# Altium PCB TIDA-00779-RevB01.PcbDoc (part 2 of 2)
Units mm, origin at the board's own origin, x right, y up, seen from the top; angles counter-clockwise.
Board outline 215 x 145 mm, 2 copper layers (Top Layer, Bottom Layer), stack 1.575 mm thick; 136 components, 56 nets, 280 pads, 32 vias.
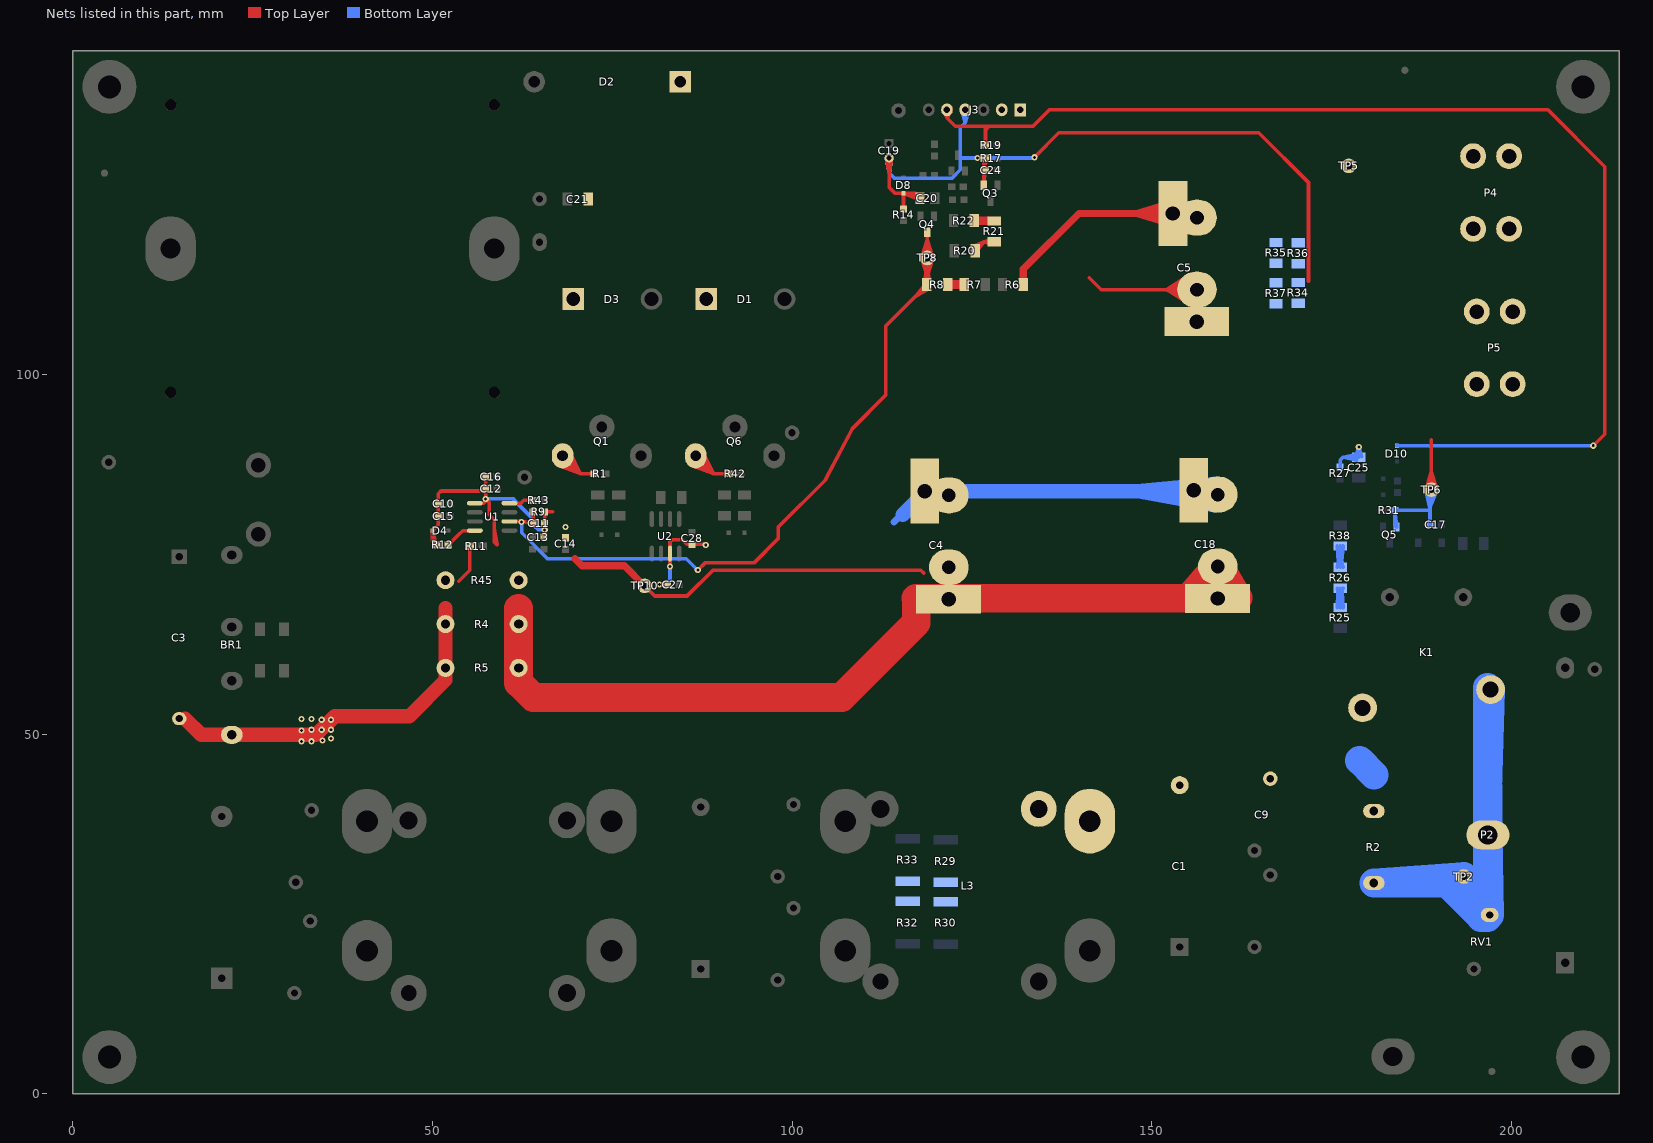
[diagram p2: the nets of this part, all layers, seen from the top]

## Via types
v1: diameter 0.864, hole 0.406, Top Layer to Bottom Layer, 32 vias

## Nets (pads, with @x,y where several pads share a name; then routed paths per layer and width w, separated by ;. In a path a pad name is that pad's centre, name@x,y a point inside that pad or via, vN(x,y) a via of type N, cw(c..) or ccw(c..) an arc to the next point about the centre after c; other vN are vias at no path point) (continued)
NetR7_1: R7.1 R8.2 | length 32.5
  Top Layer w0.5: R8.2@121.618,112.101 R7.1@123.778,112.127 ; R8.2@121.618,112.899 R7.1@123.778,112.873 ; R8.2@121.755,112.114 R7.1@123.778,112.873 ; R8.2@121.755,112.886 R7.1@123.778,112.127 ; R7.1@123.913,112.102 R8.2@121.8,112.5 ; R7.1@123.913,112.898 R8.2@121.8,112.5 ; R8.2@121.65,112.5 R7.1@123.8,112.5 ; R8.2@121.65,112.5 R7.1@123.778,112.873 ; R8.2@121.65,112.5 R7.1@123.778,112.127 ; R8.2@121.65,112.5 R7.1@123.95,112.5 R8.2@121.8,112.5 ; R7.1@123.8,112.5 121.687,112.102 R7.1@123.8,112.5 ; R7.1@123.8,112.5 121.687,112.898 R7.1@123.8,112.5
NetR12_2: R12.2 U1.4 | length 7.6
  Top Layer w0.5: R12.2@52.2,76.3 54.195,78.295 ; R12.2@52.225,76.3 53.736,77.836 ; U1.4@55.1,78.295 54.195,78.295 ; U1.4@55.9,78.295 54.195,78.295
NetR20_1: R20.1 R21.1 | length 11.3
  Top Layer w0.5: R20.1@125.246,117.819 126.7,118.45 ; R20.1@125.45,117.2 126.7,118.45 ; R20.1@125.45,117.475 126.7,118.45 ; R20.1@125.734,117.193 126.7,118.45 ; R21.1@127.754,118.056 126.7,118.45 ; R21.1@127.754,118.844 126.7,118.45 ; R21.1@127.825,118.45 126.7,118.45 ; R21.1@128.1,118.45 126.7,118.45
NetR21_2: R21.2 R22.2 | length 35.1
  Top Layer w0.5: R22.2@125.315,121.002 R21.2@127.476,121.011 ; R22.2@125.333,121.8 R21.2@127.498,121.694 ; R22.2@125.441,121.01 R21.2@127.498,121.694 ; R22.2@125.458,121.785 R21.2@127.476,121.011 ; R21.2@127.788,120.952 R22.2@125.675,121.35 ; R21.2@127.788,121.748 R22.2@125.675,121.35 ; R21.2@127.825,121.35 R22.2@125.675,121.35 ; R21.2@128.1,121.35 125.4,121.35 R22.2@125.35,121.4 ; R22.2@125.35,121.4 R21.2@127.502,121.35 ; R22.2@125.35,121.4 R21.2@127.498,121.694 ; R22.2@125.35,121.4 R21.2@127.476,121.011 ; R22.2@125.35,121.4 R21.2@127.501,121.35 ; R21.2@127.502,121.35 125.378,121.001 R21.2@127.501,121.35 ; R21.2@127.502,121.35 125.396,121.797 R21.2@127.501,121.35
NetR25_1: R25.1 R26.1 | length 24.4
  Bottom Layer w0.5: R25.1@175.8,67.581 R26.1@175.896,69.761 ; R25.1@175.802,67.637 176.2,69.75 R25.1@176.598,67.637 ; R26.1@175.802,70.263 176.2,68.15 R26.1@176.598,70.263 ; R25.1@175.811,67.692 R26.1@176.504,69.761 ; R26.1@176.2,70.3 R25.1@176.2,67.6 ; R25.1@176.589,67.692 R26.1@175.896,69.761 ; R25.1@176.6,67.581 R26.1@176.504,69.761 ; R26.1@175.896,69.761 R25.1@176.2,67.6 ; R25.1@176.2,67.6 R26.1@176.504,69.761
NetR26_2: R26.2 R38.1 | length 29.4
  Bottom Layer w0.5: R38.1@175.8,76.161 175.942,73.982 ; R26.2@175.802,73.237 176.2,75.35 ; R38.1@175.802,76.113 176.2,74 R38.1@176.598,76.113 ; R38.1@175.809,76.067 176.458,73.982 ; R26.2@176.2,73.2 R38.1@176.2,76.15 ; R38.1@176.591,76.067 175.942,73.982 ; R26.2@176.598,73.237 176.2,75.35 ; R38.1@176.6,76.161 176.458,73.982 ; 175.942,73.982 R38.1@176.2,76.15 ; 176.2,75.35 R38.1@176.2,76.15 ; 176.2,75.35 175.813,76.05 176.2,75.35 ; 176.2,75.35 176.587,76.05 176.2,75.35 ; 176.2,75.35 R38.1@176.2,76.15 ; R38.1@176.2,76.15 176.458,73.982
NetR29_2: R29.2 R30.1 R32.1 R33.2
NetR34_2: R34.2 R35.1 R36.1 R37.2
NetR43_1: R43.1 U1.8 | length 5.7
  Top Layer w0.5: U1.8@60.6,82.105 62.305,82.105 ; U1.8@61.4,82.105 62.305,82.105 ; R43.1@63.975,82.5 62.7,82.5 ; R43.1@64,82.5 62.7,82.5 ; 62.305,82.105 62.7,82.5
PFC_ON: D10.2 J3.5 R19.1 | length 171.2
  Top Layer w0.5: J3.5@120.998,136.878 121.56,135.64 ; J3.5@122.122,136.878 121.56,135.64 ; R19.1@126.9,131.9 126.9,134 ; 126.9,134.2 126.9,134 ; 127.3,134.4 126.9,134 ; v1(211.4,90.1) 213,91.7 213,128.9 205.1,136.8 135.8,136.8 133.5,134.5 122.7,134.5 121.56,135.64 ; 121.56,135.64 121.56,137 121.56,135.64
  Bottom Layer w0.5: D10.2@184.1,90.1 v1(211.4,90.1)
PGND: C4.2 C5.2 C10.2 C11.2 C12.2 C13.2 C14.2 C15.2 C16.2 C17.2 C18.2 C19.2 C20.2 C24.2 C25.2 C27.2 C28.1 D4.2 D8.1 J3.4 P5.1 P5.2 P5.3 P5.4 Q1.3 Q3.2 Q5.2 Q6.3 R1.2 R4.1 R5.1 R9.1 R12.1 R14.2 R17.1 R27.1 R31.1 R34.1 R37.1 R42.2 R45.1 TP6.1 TP10.1 U1.1 U2.3 | length 610.4
  Top Layer w0.5: R12.1@50.6,76.3 50,76.9 ; U1.1@55.9,82.105 57.105,82.105 ; v1@57.4,82.4 57.105,82.105 ; C16.2@57.4,85.8 C12.2@57.4,84.1 ; 58.6,78.557 59,76.325 ; 59,76.3 58.6,76.7 58.6,79.8 57.9,80.5 57.9,82.2 v1(57.4,82.7) C12.2@57.4,84.1 ; 61.98,67.5 62,67.52 ; C13.2@65.5,77.4 65.6,77.5 v1(65.6,78.4) ; C13.2@65.525,77.4 v1(65.6,78.4) ; R9.1@65.625,80.9 66.6,80.9 ; 66.7,80.9 66.6,80.9 ; Q1.3@67.451,87.382 70.6,86.2 ; Q1.3@67.664,87.84 70.6,86.2 ; Q1.3@67.94,88.258 70.6,86.2 ; Q1.3@68.1,88.45 70.6,86.2 ; Q1.3@68.1,88.7 70.6,86.2 ; Q1.3@68.274,88.629 70.6,86.2 ; Q1.3@68.661,88.948 70.6,86.2 ; Q1.3@69.094,89.208 70.6,86.2 ; R1.2@72.475,86.2 70.6,86.2 ; R1.2@72.5,86.2 70.6,86.2 ; TP10.1@79.5,70.6 80.9,69.2 85.4,69.2 89,72.8 117.9,72.8 118.3,72.4 ; v1(81.574,70.8) C27.2@82.7,70.8 ; v1(83.035,73.3) U2.3@83.035,75.1 83.035,76.735 83.3,77 84.8,77 85.4,76.4 C28.1@86.1,76.4 87.9,76.4 v1(88,76.3) ; Q6.3@85.951,87.382 89.1,86.2 ; Q6.3@86.164,87.84 89.1,86.2 ; Q6.3@86.44,88.258 89.1,86.2 ; Q6.3@86.6,88.45 89.1,86.2 ; Q6.3@86.6,88.7 89.1,86.2 ; Q6.3@86.774,88.629 89.1,86.2 ; Q6.3@87.161,88.948 89.1,86.2 ; Q6.3@87.594,89.208 89.1,86.2 ; 89.3,86.2 R42.2@91.275,86.2 ; R42.2@91.3,86.2 89.1,86.2 ; C19.2@113.126,130.067 113.5,127.975 ; C19.2@113.874,130.067 113.5,127.975 ; R14.2@115.5,123 D8.1@115.5,125.2 ; R14.2@115.5,123.4 D8.1@115.5,125.2 ; C20.2@117.683,124.298 D8.1@115.5,125.2 ; C20.2@117.8,124.5 117.1,125.2 ; C20.2@117.856,125.046 D8.1@115.5,125.2 ; Q3.2@126.647,126.3 R17.1@126.647,129.847 ; Q3.2@126.647,126.386 C24.2@126.875,128.4 ; C24.2@126.647,128.033 126.875,130.1 v1(125.8,130.1) R17.1@126.9,130.1 ; C24.2@126.647,128.45 126.647,126.525 C24.2@126.875,128.4 ; v1(133.7,130.2) 137.1,133.6 164.9,133.6 171.8,126.7 171.8,113 ; 141.33,113.47 143,111.8 C5.2@156.3,111.8 ; C5.2@155.417,109.641 152.05,111.8 ; C5.2@155.417,113.959 152.05,111.8 ; C5.2@155.667,110.092 152.05,111.8 ; C5.2@155.667,113.508 152.05,111.8 ; C5.2@155.855,110.565 152.05,111.8 ; C5.2@155.855,113.035 152.05,111.8 ; C5.2@155.98,111.053 152.05,111.8 ; C5.2@155.98,112.547 152.05,111.8 ; C5.2@156.042,111.55 152.05,111.8 ; C5.2@156.042,112.05 152.05,111.8 ; C5.2@156.05,111.8 152.05,111.8 ; TP6.1@188.143,84.117 188.9,86.516 ; TP6.1@188.634,84.014 188.9,86.516 ; TP6.1@188.9,84 188.9,90.9 ; TP6.1@189.166,84.014 188.9,86.516 ; TP6.1@189.657,84.117 188.9,86.516 ; 50,76.9 R12.1@50.575,76.3 ; 50,76.9 R12.1@50.575,76.3 ; 50,76.9 R12.1@50.575,76.3 ; 50,76.9 D4.2@50,78.3 ; 50,76.9 D4.2@50,78.3 ; D4.2@50,78.3 R12.1@50.575,76.3 ; D4.2@50,78.3 R12.1@50.575,76.3 ; D4.2@50,78.3 50.8,79.1 ; 50.8,79.1 C15.2@50.8,80.3 ; 50.8,79.1 C15.2@50.8,80.3 ; C15.2@50.8,80.3 C10.2@50.8,82 ; C15.2@50.8,80.3 C10.2@50.8,82 ; C10.2@50.8,82 50.8,83.4 51.2,83.8 57.1,83.8 C12.2@57.4,84.1 ; 57.105,82.105 56.7,82.105 57.105,82.105 ; v1(65.6,78.4) C11.2@65.6,79.3 ; v1(65.6,78.4) C11.2@65.6,79.3 ; C11.2@65.6,79.3 R9.1@65.6,80.9 ; C11.2@65.6,79.3 R9.1@65.6,80.9 ; R9.1@65.6,80.9 66.6,80.9 ; 113.5,127.975 C19.2@113.5,130.1 113.5,126 114.3,125.2 ; 114.3,125.2 D8.1@115.5,125.2 ; 114.3,125.2 D8.1@115.5,125.2 ; D8.1@115.5,125.2 C20.2@117.8,124.665 ; D8.1@115.5,125.2 117.1,125.2 ; 117.1,125.2 C20.2@117.8,124.665 ; 117.1,125.2 117.961,125.015 117.1,125.2 ; 117.1,125.2 117.505,124.418 117.1,125.2 ; 117.1,125.2 C20.2@117.8,124.665 ; R17.1@126.647,129.847 R17.1@126.9,130.1 ; R17.1@126.647,129.847 C24.2@126.875,128.4 ; C24.2@126.875,128.4 R17.1@126.9,130.1 ; R14.2@115.5,123.025 115.5,125 R14.2@115.5,123.025
  Top Layer w1: 69.8,74.4 70.8,73.4 76.7,73.4 TP10.1@79.5,70.6
  Top Layer w4: 61.98,67.5 61.98,57.12 64,55.1 106.9,55.1 117.275,65.475 C4.2@117.275,68.881 ; 117.241,68.881 C4.2@117.275,68.881 ; 142.665,68.881 C18.2@156.666,68.85 ; C18.2@158.95,73.3 C18.2@155.166,68.95 ; C18.2@159.45,73.3 162.05,68.95 C18.2@155.166,68.95 ; C4.2@117.275,68.881 155.097,68.881 C18.2@155.166,68.95
  Bottom Layer w0.5: v1(57.4,82.7) 61.3,82.7 ; 61.2,82.7 64.2,79.7 64.2,78.9 64.7,78.4 v1(65.6,78.4) ; v1(81.574,70.8) 82.4,70.8 83.035,71.435 v1(83.035,73.3) ; C19.2@113.127,130.066 113.5,128.05 ; C19.2@113.873,130.066 113.5,128.05 ; J3.4@123.531,136.917 124.1,135 ; J3.4@124.669,136.917 124.1,135 ; v1(133.7,130.2) 133.6,130.1 v1(125.8,130.1) 123.5,130.1 123.4,130 ; R27.1@176.2,87.1 176.2,88.1 ; R27.1@176.2,87.125 176.2,88.1 ; C25.2@178.404,88.557 v1(178.8,89.9) ; C25.2@178.483,88.102 176.6,88.5 ; C25.2@178.483,88.898 176.6,88.5 ; C25.2@178.525,88.5 176.6,88.5 ; C25.2@179.196,88.557 v1(178.8,89.9) ; Q5.2@183.8,79.125 R31.1@183.8,81.1 ; R31.1@183.8,80.99 184.053,79.025 R31.1@183.8,80.997 ; R31.1@183.825,81.1 185.8,81.1 ; Q5.2@184.053,78.8 183.8,79.053 R31.1@183.8,81.1 ; TP6.1@188.136,83.944 188.7,81.474 ; TP6.1@188.634,84.007 188.7,81.474 ; C17.2@188.7,79.1 188.7,81.1 ; TP6.1@189.164,83.965 188.7,81.474 ; TP6.1@189.646,83.825 188.7,81.474 ; 113.5,128.05 C19.2@113.5,130.1 113.5,128.05 ; 113.5,128.05 114.25,127.3 122.25,127.3 123.4,128.45 123.4,130 ; 123.4,130 123.4,134.3 124.1,135 ; 124.1,135 124.1,137 124.1,135 ; 176.2,88.1 176.6,88.5 ; 176.6,88.5 C25.2@178.8,88.5 v1(178.8,89.9) ; R31.1@183.8,81.1 188.7,81.1 ; 188.7,81.1 188.7,83.8 TP6.1@188.9,84 188.7,81.474
  other v1: 68.5,78.8
RLY-N: ?.4@134.3,39.6 C1.2 C9.1 K1.4 L3.4 R2.2 | length 4.8
  Bottom Layer w4: L3.4@141.4,37.9 L3.4@142.8,39.3 ; 178.9,46.33 180.9,44.33
RLY-P: K1.3 P2.1 R2.1 RV1.1 TP2.1 | length 175.7
  Bottom Layer w4: 196.7,42.158 K1.3@197.127,56.19 ; 196.7,49.975 P2.1@196.749,35.975 ; K1.3@196.7,56.47 P2.1@196.7,35.975 ; 191,29.3 195.8,24.5 ; 191,29.3 TP2.1@193.4,30.2 ; 191,29.3 TP2.1@193.4,30.2 ; 191,29.3 TP2.1@193.4,30.2 ; 191,29.3 TP2.1@193.4,30.2 ; 191,29.3 196.75,24.85 TP2.1@193.4,30.2 ; 191,29.3 181.4,29.3 TP2.1@193.4,30.2 ; 191,29.3 R2.1@180.9,29.3 TP2.1@193.4,30.2 ; TP2.1@193.4,30.2 195.8,24.5 ; 195.8,24.5 RV1.1@196.7,24.5 ; RV1.1@196.7,24.5 P2.1@196.7,35.975 ; RV1.1@196.7,24.5 P2.1@196.749,35.975 ; P2.1@196.7,35.975 RV1.1@197,24.85 P2.1@196.749,35.975
RTN: BR1.4 C3.2 R4.2 R5.2 R11.1 R45.2 | length 67
  Top Layer w0.5: 53.65,71.25 55.2,72.8 R11.1@55.2,76.1
  Top Layer w2: C3.2@15.6,52.15 17.85,49.9 ; BR1.4@21.85,49.9 17.85,49.9 ; BR1.4@22.35,49.9 29.6,49.9 ; 51.82,67.5 51.82,57.52 46.8,52.5 36.4,52.5 33.8,49.9 BR1.4@22.1,49.9 17.85,49.9
  other v1: 31.8,49 33.2,49 34.7,49.1 35.9,49.4 31.8,50.5 33.2,50.6 34.6,50.6 35.9,50.6 34.6,52 35.9,52 31.8,52.1 33.2,52.1
VDCBUS: C4.1 C5.1 C18.1 C21.1 D1.2 D2.1 D3.2 P4.1 P4.2 P4.3 P4.4 R6.2 R35.2 R36.2 TP5.1 | length 189.3
  Top Layer w1: R6.2@132.15,112.5 132.15,114.65 ; R6.2@132.15,112.775 132.15,114.65 ; C5.1@152.725,120.905 147.95,122.388 ; C5.1@152.725,123.871 147.95,122.388 ; C5.1@152.925,121.889 147.95,122.388 ; C5.1@152.925,122.887 147.95,122.388 ; C5.1@152.95,122.388 139.888,122.388 132.15,114.65
  Bottom Layer w1: 114.162,79.5 C4.1@118.45,83.788
  Bottom Layer w2: 115.4,80.5 C4.1@118.1,83.2 ; C4.1@118.1,83.788 C4.1@118.45,83.788 C18.1@156.274,83.788 ; C18.1@156.55,83.512 C18.1@156.274,83.788 ; C18.1@158.328,81.935 C18.1@155.85,83.888 ; C18.1@158.733,81.816 150.413,83.788 ; C18.1@158.783,81.809 147.848,83.788 ; C18.1@158.871,84.798 C18.1@155.85,83.888 ; C18.1@158.904,84.799 150.413,83.788 ; C18.1@158.915,84.8 147.848,83.788 ; 147.848,83.788 C18.1@158.95,83.3 ; 147.848,83.788 C18.1@155.85,83.888 ; 150.413,83.788 C18.1@158.95,83.3 ; C18.1@155.85,83.888 C18.1@158.95,83.3 ; C18.1@156.274,83.788 C18.1@158.95,83.3 ; C18.1@156.274,83.788 158.802,84.793 C18.1@156.274,83.788 ; C18.1@156.274,83.788 158.284,81.956 C18.1@156.274,83.788 ; C18.1@156.274,83.788 C18.1@158.95,83.3
VN: J3.2
VP: J3.1
VSENSE: C11.1 Q4.3 R8.1 R9.2 TP8.1 U1.6 | length 141.2
  Top Layer w0.5: U1.6@60.6,79.565 v1@62.335,79.565 ; U1.6@61.4,79.565 v1@62.335,79.565 ; C11.1@63.975,79.3 v1(62.4,79.5) ; v1(86.9,72.8) 87.9,73.8 94.7,73.8 98.1,77.2 98.1,78.8 104.6,85.3 108.4,92.5 113,97.1 113,106.7 118.8,112.5 Q4.3@118.8,119.8 ; TP8.1@118.043,116.083 118.8,113.684 ; TP8.1@118.043,116.317 118.8,118.716 ; R8.1@118.353,112.821 118.8,114.926 ; R8.1@118.462,112.503 117.061,110.761 ; TP8.1@118.534,116.186 118.8,113.684 ; TP8.1@118.534,116.214 118.8,118.716 ; R8.1@118.75,112.225 117.061,110.761 ; R8.1@118.75,112.775 118.8,114.926 ; 118.8,117.65 Q4.3@118.8,119.575 ; R8.1@118.984,111.901 117.061,110.761 ; TP8.1@119.066,116.186 118.8,113.684 ; TP8.1@119.066,116.214 118.8,118.716 ; R8.1@119.149,112.803 118.8,114.926 ; TP8.1@119.557,116.083 118.8,113.684 ; TP8.1@119.557,116.317 118.8,118.716 ; v1@62.335,79.565 v1(62.4,79.5) ; v1(62.4,79.5) 63.8,79.5 C11.1@64,79.3 ; C11.1@64,79.3 R9.2@64,80.9 C11.1@64,79.3 ; 118.8,113.684 TP8.1@118.8,116.2 118.8,118.716
  Bottom Layer w0.5: v1(62.4,79.5) 62.4,78 66,74.4 85.3,74.4 v1(86.9,72.8)
pads on no net: FID1.1 FID2.1 FID3.1 H1.1 H2.1 H3.1 H4.1 L1.3 U2.1 U2.8

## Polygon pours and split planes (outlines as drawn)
RTN on Bottom Layer "Bottom Layer-No Net 13" (solid, pour order 73): 14.9,53.1 36,53.1 36.9,52.2 36.9,49.7 35.9,48.7 35.6,48.4 17.8,48.4 16.4,48.4 14.4,50.4 14.4,52.6 14.754,52.954
RLY-N on Bottom Layer "Bottom Layer-No Net 5" (solid, pour order 50): 132.4,33.3 154.9,33.3 159.9,38.3 169.6,38.3 169.5,38.4 184.7,38.4 186,39.7 186,53.9 183.8,56.1 144.5,56.1 131.3,42.9 131.3,34.4
NetC1_1 on Bottom Layer "Top Layer-No Net 3" (solid, pour order 46): 176,24.8 177.1,23.7 188.4,23.7 192.6,19.5 201.3,19.5 204,22.2 213,22.2 213.4,21.8 213.4,15.4 206.9,11.1 178.3,11.1 176.2,13.2 146.1,13.2 142.8,9.9 133,9.9 131.4,11.5 131.4,23.5 132.7,24.8
NetC2_2 on Bottom Layer "M1 Board Outline-No Net" (solid, pour order 39): 112.2,47.7 117.3,42.6 123.4,42.6 123.6,42.4 123.6,35.4 123,34.9 114.4,34.9 112.9,33.4 103.5,33.4 102.4,34.5 94.6,34.5 89.9,29.8 66.8,29.8 65,31.6 65,45.6 67.1,47.7
NetBR1_3 on Bottom Layer "Bottom Layer-No Net 4" (solid, pour order 42): 38.9,24.4 48.2,24.4 50.4,22.2 50.4,4.3 48.1,2 18,2 0.9,19.1 0.9,62.9 2.5,64.5 15.3,64.5 19.8,60 23.7,60 24.1,59.6 24.1,55.8 23.6,55.3 12.8,55.3 11.3,53.8 11.3,48.4 14.9,44.8 14.9,31.8 26.9,19.8 34.3,19.8
NetBR1_2 on Bottom Layer "Bottom Layer-No Net 3" (solid, pour order 41): 18.6,45.4 46.6,45.4 49.7,42.3 49.7,35.6 47.5,33.4 19.9,33.4 18.2,35.1 18.2,45
NetF1_2 on Bottom Layer "Top Layer-No Net 16" (solid, pour order 64): 205.3,72.5 205.3,57.3 205.8,56.8 212.2,56.8 212.9,57.5 212.9,75.7 212.2,76.4 209.2,76.4
VDCBUS on Bottom Layer "Bottom Layer-No Net" (solid, pour order 38): 144.1,133.2 115.5,104.6 115.5,93.7 111.8,90 111.8,80.2 113,79 117.2,79 160.8,79.1 162.4,80.7 162.4,95.7 158.8,99.3 149.1,99.3 146.5,101.9 146.5,115.7 148.5,117.7 206.5,117.7 207.8,119 207.8,129 203.6,133.2
VDCBUS on Bottom Layer "Bottom Layer-No Net 11" (solid, pour order 70): 68.2,125.8 69.2,126.8 103.2,126.8 117.5,112.5 124.3,112.5 115,103.2 108.2,103.2 107,104.4 102.9,104.4 104.6,106.1 104.6,112.8 101.4,116 97.1,116 93.8,112.7 93.8,107.5 93.2,106.9 87.794,106.9 86.2,108.494 86.2,115.2 85.4,116 77.9,116 75.1,113.2 75.1,109 74.4,108.3 74.2,108.5 68.2,108.5
NetBR1_1 on Bottom Layer "Bottom Layer-No Net 12" (solid, pour order 71): 20.5,79.4 20.5,73.9 20.9,73.5 26.9,73.5 27.3,73.9 27.3,78.8 26.6,79.5 20.6,79.5 20.5,79.4
NetC3_1 on Bottom Layer "Bottom Layer-No Net 2" (solid, pour order 40): 28.5,142.8 66.786,142.901 67.7,141.9 67.7,135.1 62.5,130 42.4,130 37.6,125.5 37.7,89.7 33,85 18.2,84.9 16.8,83.6 16.8,73.85 16.414,73.4 3.6,73.4 2.6,74.4 2.6,116.8 27.4,141.6
VDCBUS on Bottom Layer "Bottom Layer-No Net 10" (solid, pour order 69): 67.6,113.2 67.6,99.1 68.7,98 69,97.7 90.5,97.7 102.5,97.7 112.9,87.3 117.5,91.9 117.5,103.1 117.5,104.8 116.9,105.4 116.8,105.5 95.7,105.5 93,108.2 93,112.8 92.4,113.4 86.9,113.4 86.1,112.6 86.1,109.194 86.8,108.494 87.2,108.094 87.2,105.6 86.9,105.6 86.7,105.4 75.5,105.4 74.4,106.5 74.4,112.9 73.4,113.9 68.3,113.9 67.6,113.2
PGND on Bottom Layer "Bottom Layer-No Net 7" (solid, pour order 66): 122.5,75.89 108.81,75.89 101.1,83.6 94.1,83.6 87.2,90.5 84.1,90.5 83.7,90.1 83.7,86 81.4,83.7 74.6,83.7 73.3,85 73.3,87 69.4,90.9 66.9,90.9 66,90 66,78.6 67.5,77.1 84.3,77.1 88.9,72.5 95.4,72.5 105.5,62.4 124.4,62.4 130.6,68.6 130.6,69.8
PGND on Bottom Layer "Bottom Layer-No Net 9" (solid, pour order 65): 160.7,75.8 119.6,75.8 118.2,74.4 116.5,72.7 116.5,67.49 116.5,66.7 117.1,66.1 117.69,66.69 161.8,66.69 163.29,66.69 163.9,67.3 163.9,75 163.1,75.8
PGND on Bottom Layer "Bottom Layer-No Net 8" (solid, pour order 56): 171.2,110.5 164,110.5 161.8,112.7 160.3,114.2 155.1,114.2 152.8,114.2 151.8,113.2 151.8,105 152.1,104.7 169.7,104.7 171.2,106.2
RLY-P on Bottom Layer "Bottom Layer-No Net 6" (solid, pour order 52): 178,35 186,35 189.3,38.3 189.3,60 190.3,61 200.9,61 201.8,60.1 201.8,24.8 199.7,22.7 194.6,22.7 192.3,25 190.4,26.9 180.6,26.9 179,26.9 177.6,28.3 177.6,34.6 178,35
NetC2_1 on Bottom Layer "Top Layer-No Net 2" (solid, pour order 45): 69.8,24.8 88.7,24.8 91.9,21.6 101.9,21.6 104.5,24.2 112.4,24.2 115,21.6 122.8,21.6 123.5,20.9 123.5,4.7 120.8,2 67.6,2 66.1,3.5 66.1,21.1
VDCBUS on Top Layer "Top Layer-No Net 9" (solid, remove dead copper, pour order 67): 82.1,143.3 80.1,141.3 80.1,129.4 69.7,121.9 69.7,116.3 67.7,114.3 67.7,109 68.1,108.6 74.7,108.6 75,108.9 75,114.3 76.6,115.9 85.6,115.9 86.1,115.4 86.1,109.2 86.6,108.7 92.5,108.7 93,109.2 93,114.1 101.546,122.646 101.546,141.854 100.1,143.3
NetBR1_2 on Top Layer "Top Layer-No Net 7" (solid, pour order 53): 49,42.5 49.7,41.8 49.7,34.4 48.7,33.4 28.1,33.4 23.5,28.8 20.8,31.5 20.8,32.5 14.1,42.5
NetBR1_3 on Top Layer "Top Layer-No Net 12" (solid, pour order 59): 39.2,23.9 34.3,19 15.6,19 14.3,17.7 14.3,4.5 16.2,2.6 46.8,2.6 49.9,5.7 49.9,22.3 48,24.2 39.4,24.2 39.1,23.9
PGND on Top Layer "Top Layer-No Net 17" (solid, remove dead copper, pour order 72): 51.1,73.9 75.725,73.9 79.3,68.7 86.5,68.7 88.7,73.2 88.7,82.6 87.6,83.7 49.6,83.7 49.6,75.4
RLY-N on Top Layer "Top Layer-No Net 10" (solid, pour order 57): 131.4,35.7 131.4,42.5 133.7,44.8 169,44.8 172.2,48 172.2,55 173,55.8 183,55.8 183.4,55.4 183.4,39.1 182.7,38.4 158.6,38.4 153.6,33.4 133.7,33.4
NetC2_1 on Top Layer "Top Layer-No Net 5" (solid, pour order 49): 67.6,2 113.9,2 115.6,3.7 115.6,18.9 110.4,24.1 105.4,24.1 102.4,21.1 93,21.1 89.8,24.3 69.8,24.3 66.4,20.9 66.4,3.2
NetC2_2 on Top Layer "M1 Board Outline-No Net" (solid, pour order 48): 114.6,42.4 115.6,41.4 115.6,34.1 114.7,33.2 103.5,33.2 102.4,34.3 66.2,34.3 65.2,35.3 65.2,41 66.6,42.4
NetC1_1 on Top Layer "Top Layer-No Net 11" (solid, remove dead copper, pour order 58): 162.5,24.4 165.3,21.6 165.3,11.7 163.3,9.7 134.3,9.7 131.3,12.7 131.3,22.1 133.6,24.4
PGND on Top Layer "Top Layer-No Net 6" (solid, pour order 54): 207.1,112 208.3,110.8 208.3,92.7 206.616,91.1 193.3,91.1 191.5,89.3 166.1,89.3 159.5,95.9 151.4,95.9 148.2,99.1 148.2,111.69 150.61,114.1 176.9,114.1 181.1,109.9 189.8,109.9 191.9,112
NetD1_1 on Top Layer "Bottom Layer-No Net 1" (solid, pour order 68): 92.9,90.9 98.2,96.2 103.2,96.2 106.9,99.9 106.9,112.5 105.4,114 97.6,114 96.2,112.6 96.2,107.4 94.2,105.4 85.9,105.4 83.9,107.4 83.9,112.7 83.4,113.2 78.6,113.2 78,112.6 78,106.8 76.5,105.3 66,105.3 64.5,106.8 64.5,114.8 66,117.7 65.9,119.8 62.1,119.9 59.1,122.5 52.3,122.4 50.7,122.4 49.4,121.1 49.5,98.6 54,94.1 69.2,94.1 72.6,90.7 74.8,90.7 77.4,93.3 88.1,93.3 90.5,90.9
NetF1_2 on Top Layer "Top Layer-No Net 16" (solid, pour order 63): 205.3,75.7 205.3,57.3 205.8,56.8 212.2,56.8 212.9,57.5 212.9,75.7 212.2,76.4 206,76.4 205.3,75.7
GNDE on Top Layer "Top Layer-No Net 15" (solid, pour order 62): 34.3,28.4 32.2,30.5 30.4,30.5 29.8,29.9 29.8,28.7 29.8,24.8 31.5,23.1 31.6,23 33.6,23 34.4,23.8 34.7,24.1 34.7,26.3 34.7,26.9 35.5,27.7
GNDE on Top Layer "Top Layer-No Net 14" (solid, pour order 61): 160,29.4 161.8,31.2 161.8,32.8 161.8,33.9 162.6,34.7 162.7,34.8 165.6,34.8 167.7,32.7 167.7,29 167.7,25 167.6,25 163.7,28.9
GNDE on Top Layer "Top Layer-No Net 13" (solid, pour order 60): 95.2,27.8 98.2,24.8 100.6,24.8 104,28.2 104,28.6 102.2,28.6 100,30.8 99.6,31.2 97.3,31.2 97.3,31.15 94.55,28.4
PGND on Top Layer "Top Layer-No Net 8" (solid, pour order 55): 124.4,74.7 126.6,74.7 129.8,77.9 129.8,102.8 141.2,114.2 152.6,114.2 152.6,97.1 146.2,90.7 146.2,77.8 149.5,74.5
RLY-P on Top Layer "Bottom Layer-No Net 6" (solid, pour order 51): 178,35 186,35 189.3,38.3 189.3,60 190.3,61 200.9,61 201.8,60.1 201.8,24.8 199.7,22.7 194.6,22.7 192.3,25 190.4,26.9 180.6,26.9 179,26.9 177.6,28.3 177.6,34.6 178,35
RTN on Top Layer "Top Layer-No Net 1" (solid, pour order 44): 19.8,53.1 31.3,53.1 33.6,55.4 35.2,57 43,57 44.1,57 46.2,59.1 46.2,71.1 48,72.9 52.9,72.9 55.3,72.9 55.3,70.5 55.3,59.2 55.3,47.8 53.5,46 53.3,45.8 50.4,45.8 19,45.8 14.8,50 13.8,51 13.8,52.6 14.3,53.1 16.4,53.1
NetBR1_2 on Top Layer "Top Layer-No Net" (solid, pour order 43): 23.8,70.3 2.2,70.3 0.9,69 0.9,29.4 3.6,26.7 21.45,26.7 23.6,28.85 23.6,36.7 23.6,39.4 22.6,40.4 18.9,40.4 11.2,48.1 11.3,48.2 11.3,54.1 20.2,63 22.4,63 25.9,63 26.4,63.5 26.4,69.6 25.8,70.2
PGND on Top Layer "Top Layer-No Net 4" (solid, pour order 47): 60,71.7 60,47.5 61.6,45.9 126.9,45.9 130.8,49.8 165.8,49.8 166.6,50.6 166.6,75.3 166.2,75.7 113.3,75.7 105.7,72.7 107.847,70.553 107.847,66 101.392,61.8 68.6,61.8 67.6,62.8 67.6,72.7 61,72.7

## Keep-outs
Keep-Out Layer:
  circle w0.254: c108.15,138.5 r1.75
  circle w0.254: c199.25,84.2 r1.75
  circle w0.254: c41.55,82.8 r1.75
  lines w0.2: 147.2,2.1 147.2,12.6 175.2,12.6 175.2,2.1 147.2,2.1
  lines w0.254: -0.127,87.63 cw(c0,87.63) 0,87.757 ccw(c0,87.63) -0.127,87.63 ; 0,1.336 215,1.336 215,145 0,145 0,1.336
  lines w1: 12.7,49.8 12.7,53.3 13.6,54.2 15.2,54.2 ; 68.5,92.6 69.5,91.6 71.5,89.6 75.7,89.6 77.9,91.8 85.7,91.8 87.9,91.8 90.4,89.3 93.6,89.3 94.3,90 96.9,92.6 ; 85.1,113.5 85.1,107.8 85.9,107
  lines w1.2: 13.7,54.2 23,54.2 ; 20.2,61.5 24.4,61.5

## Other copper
Top Layer:
  rectangle net VDCBUS: 71,121.6 73,124.5
  rectangle net VDCBUS: 71.7,122.7 75.9,125.3
  rectangle net PGND: 60.3,69 61.1,69.9
  rectangle net NetD12_1: 84.257,80.2 85.3,82.4
Bottom Layer:
  rectangle net NetR34_2: 166.3,112.2 171.3,116.1
  rectangle net NetR29_2: 114.5,26.2 123,30

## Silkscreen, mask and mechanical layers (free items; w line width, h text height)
Top Overlay:
  text "VN" at 129.8,138.9 h1.6 r90
  text "VP" at 132.3,138.9 h1.6 r90
  text "VCC" at 127.2,138.8 h1.6 r90
  text "GND" at 124.6,138.7 h1.6 r90
  text "ACSE" at 119.3,138.6 h1.6 r90
  text "PFC ON" at 122,138.6 h1.6 r90
  text "390VDC" at 190.2,119.9 h3 r90
  text "PGND" at 190.2,99.5 h3 r90
  text "L" at 207.6,72 h3
  text "N" at 195.5,40.7 h3
  text "E" at 188.8,6.2 h3
  text "TIDA-00779" at 79.26,3.8 h3
  text "Rev B" at 94.5,3.8 h3
Bottom Overlay:
  text "Rev B" at 36.3,133.7 h3
  text "TIDA-00779" at 51.7,133.7 h3
Top Paste:
  text ".Layer_Name" at 14.656,-21.806 h1.52
Bottom Paste:
  text ".Layer_Name" at 14.656,-21.806 h1.52
Bottom Solder:
  drawing of 476 lines, arcs and shapes, not listed
Drill Guide:
  text ".Layer_Name" at 14.656,-21.806 h1.52
M2 Board Dimensions:
  rectangle: 3.175,-10.16 12.7,-6.985
  rectangle: 0,-6.985 3.175,-3.81
  lines w0.178: 0,-6.985 25.4,-6.985 ; 3.175,-10.16 3.175,-3.81 ; 6.35,-10.16 6.35,-3.81 ; 12.7,-10.16 12.7,-3.81 ; 19.05,-10.16 19.05,-3.81 ; 0,-10.16 0,-3.81 25.4,-3.81 25.4,-10.16 0,-10.16
  text ".Layer_Name" at 14.656,-21.806 h1.52
M3 3D STEP Top:
  text ".Layer_Name" at 14.656,-21.806 h1.52
M4 3D STEP Bottom:
  text ".Layer_Name" at 14.656,-21.806 h1.52
M5 Assembly Top:
  lines w0.254: -7.417,-23.626 160.223,-23.626 ; -7.417,-18.462 160.274,-18.462 ; -7.417,-13.297 -7.417,-28.791 94.31,-28.791 160.274,-28.791 160.274,-13.297 -7.404,-13.297 -7.404,-28.791 32.614,-28.791 ; 55.194,-28.791 55.194,-13.297 ; 87.376,-18.462 87.376,-13.297 ; 108.712,-18.462 108.712,-13.297 ; 124.511,-28.956 124.511,-23.804
  text "COMPONENTS MARKED 'DNP' SHOULD NOT BE POPULATED." at 29.299,-8.09 h1.52
  text "ASSEMBLY VARIANT:" at 29.286,-11.024 h1.52
  text ".VariantName" at 55.601,-11.024 h1.52
  text "PCB VIEWED FROM TOP SIDE" at -5.804,-16.654 h1.52
  text "BOARD #:" at 57.099,-16.654 h1.52
  text ".PRJ_Number" at 70.955,-16.654 h1.52
  text "REV:" at 92.405,-16.654 h1.52
  text "B" at 99.809,-16.654 h1.52
  text "SVN REV:" at 113.69,-16.654 h1.52
  text ".VersionControl_RevNumber" at 126.543,-16.654 h1.52
  text "TID #:" at 57.099,-21.819 h1.52
  text "TIDA-00779" at 70.955,-21.819 h1.52
  text "PLOT NAME =" at -5.804,-27.034 h1.52
  text ".plot_File_Name" at 14.656,-27.034 h1.52
  text "GENERATED    :" at 57.15,-27.034 h1.52
  text ".Print_Date" at 79.235,-27.034 h1.52
  text ".Print_Time" at 97.752,-27.034 h1.52
  text "TEXAS INSTRUMENTS" at 129.87,-27.034 h1.52
M6 Assembly Bottom:
  lines w0.254: -7.429,-18.474 160.261,-18.474 ; -7.379,-23.639 160.261,-23.639 ; 28.334,-28.969 28.334,-23.817 ; 44.133,-18.474 44.133,-13.31 ; 65.468,-18.474 65.468,-13.31 ; 97.65,-28.804 97.65,-13.31 ; 120.231,-28.804 160.249,-28.804 160.249,-13.31 -7.429,-13.31 -7.429,-28.804 58.534,-28.804 160.261,-28.804 160.261,-13.31
  text "COMPONENTS MARKED 'DNP' SHOULD NOT BE POPULATED." at 154.991,-8.077 h1.52
  text ".VariantName" at 128.473,-11.024 h1.52
  text "ASSEMBLY VARIANT:" at 154.864,-11.024 h1.52
  text ".VersionControl_RevNumber" at 26.302,-16.667 h1.52
  text "SVN REV:" at 39.154,-16.667 h1.52
  text ".PCB_Rev" at 53.035,-16.667 h1.52
  text "REV:" at 60.439,-16.667 h1.52
  text ".PRJ_Number" at 81.89,-16.667 h1.52
  text "BOARD #:" at 95.745,-16.667 h1.52
  text "PCB VIEWED FROM BOTTOM SIDE" at 158.648,-16.667 h1.52
  text ".TID" at 81.89,-21.831 h1.52
  text "TID #:" at 95.745,-21.831 h1.52
  text "TEXAS INSTRUMENTS" at 22.974,-27.047 h1.52
  text ".Print_Time" at 55.093,-27.047 h1.52
  text ".Print_Date" at 73.609,-27.047 h1.52
  text "GENERATED    :" at 95.694,-27.047 h1.52
  text ".plot_File_Name" at 138.189,-27.047 h1.52
  text "PLOT NAME =" at 158.648,-27.047 h1.52
M9 Title Sheet:
  drawing of 57 lines, arcs and shapes, not listed
  text "1" at 18.792,204.127 h1.78
  text "2" at 82.182,204.127 h1.78
  text "3" at 145.411,204.127 h1.78
  text "4" at 209.08,204.127 h1.78
  text "5" at 272.555,204.127 h1.78
  text "6" at 336.182,204.127 h1.78
  text "A" at -10.579,175.095 h1.78
  text "A" at 365.341,175.095 h1.78
  text "B" at -10.579,114.643 h1.78
  text "B" at 365.341,114.643 h1.78
  text "C" at -10.579,54.318 h1.78
  text "C" at 365.341,54.318 h1.78
  text "PROJECT TITLE:" at 288.125,7.048 h1.14
  text "TIDA-00779" at 289.395,3.662 h1.78
  text "DESIGNED FOR:" at 288.125,-0.597 h1.14
  text "D" at -10.579,-5.88 h1.78
  text "D" at 365.341,-5.88 h1.78
  text "FILE NAME:" at 288.125,-8.217 h1.14
  text "High Efficiency and Competitive 3k5w PFC" at 289.395,-11.265 h1.78
  text "Texas Instruments (TI) and/or its licensors do not warrant the accuracy or completeness of this specification" at 161.9,-15.376 h1.14
  text "ENGINEER:" at 288.125,-15.583 h1.14
  text "LAYOUT BY:" at 326.352,-15.583 h1.14
  text "or any information contained therein. TI and/or its licensors do not warrant that this design will meet" at 160.757,-18.237 h1.14
  text "Yuan Tao" at 289.7,-19.1 h1.78
  text "Yuan Tao" at 327.94,-19.1 h1.78
  text "the specifications, will be suitable for your application or fit for any particular purpose, or will operate in" at 160.757,-21.099 h1.14
  text "ALTIUM DESIGNER VERSION:" at 326.352,-23.457 h1.14
  text "an implementation. TI and/or its licensors do not warrant that the design is production worthy. You should" at 160.757,-23.961 h1.14
  text "completely validate and test your design implementation to confirm the system functionality for your application." at 161.9,-26.822 h1.14
  text ".print_Scale" at 289.395,-26.843 h1.78
  text ".Application_BuildNumber" at 327.635,-26.843 h1.78
  text "1" at 18.792,-32.093 h1.78
  text "2" at 82.182,-32.093 h1.78
  text "3" at 145.411,-32.093 h1.78
  text "4" at 209.08,-32.093 h1.78
  text "5" at 272.555,-32.093 h1.78
  text "6" at 336.182,-32.093 h1.78
M10 Fab Notes:
  drawing of 185 lines, arcs and shapes, not listed
  text "DESIGN INFORMATION" at 314.478,150.114 h1.52
  text "MIN. TRACK WIDTH:" at 298.106,145.542 h1.52
  text "8" at 325.951,145.542 h1.52
  text "MIL" at 329.881,145.542 h1.52
  text "MIN. CLEARANCE:" at 298.106,142.189 h1.52
  text "0.2" at 324.427,142.189 h1.52
  text "mm" at 329.881,142.189 h1.52
  text "MIN. VIA PAD SIZE:" at 298.106,138.836 h1.52
  text "24" at 325.189,138.836 h1.52
  text "MIL" at 329.881,138.836 h1.52
  text "0.05mm (2MIL)" at 315.759,135.237 h1.52
  text "MINIMUM ANNULAR RING" at 289.744,135.128 h1.52
  text "EXTERNAL" at 333.742,135.128 h1.52
  text "PER" at 294.824,132.131 h1.52
  text "IPC-D-275 CLASS 2 LEVEL C" at 300.412,132.131 h1.52
  text "MIL, HOLES" at 338.213,129.279 h1.52
  text "+/-" at 328.244,129.261 h1.52
  text "+/-" at 349.936,129.261 h1.52
  text "REGISTRATION TOLERANCES:" at 289.744,129.134 h1.52
  text "METAL" at 320.218,129.134 h1.52
  text "5" at 334.853,129.134 h1.52
  text "3" at 356.012,129.134 h1.52
  text "MIL" at 358.964,129.134 h1.52
  text "MATERIAL:" at 287.844,123.813 h1.52
  text "FR-4 High Tg" at 312.9,120.249 h1.52
  text "FR-408" at 298.538,120.031 h1.52
  text "X" at 309.003,120.031 h1.52
  text "OTHER" at 336.333,120.031 h1.52
  text "62 MIL (1.6mm) +/-10%" at 306.668,115.898 h1.52
  text "THICKNESS:" at 289.744,115.789 h1.52
  text "X" at 303.413,115.789 h1.52
  text "OTHER" at 339.305,115.789 h1.52
  text "TOLERANCE:" at 289.744,111.776 h1.52
  text "X" at 311.062,111.776 h1.52
  text "ANSI IPC-6012 TYPE 3 CLASS 2" at 315.81,111.776 h1.52
  text "OTHER +/-" at 315.81,107.814 h1.52
  text "BOW & TWIST:" at 289.744,103.826 h1.52
  text "X" at 311.062,103.826 h1.52
  text "ANSI IPC-6012 TYPE 3 CLASS 2" at 315.81,103.826 h1.52
  text "OTHER +/-" at 315.81,99.8 h1.52
  text "DRILLING:" at 287.844,96.282 h1.52
  text "REFERENCE:" at 289.744,93.31 h1.52
  text "X" at 306.209,93.31 h1.52
  text "AS SHOWN" at 310.958,93.31 h1.52
  text "X" at 329.094,93.31 h1.52
  text "NC_DRILL FILES" at 332.574,93.31 h1.52
  text "PTH MIN COPPER THICKNESS:" at 289.744,89.297 h1.52
  text "X" at 324.039,89.297 h1.52
  text "1MIL" at 327.519,89.297 h1.52
  text "OTHER" at 340.143,89.297 h1.52
  text "BOARD FINISH:" at 287.844,85.259 h1.52
  text "SILKSCREEN:" at 291.787,82.261 h1.52
  text "X" at 315.886,82.261 h1.52
  text "TOP" at 319.086,82.261 h1.52
  text "X" at 328.84,82.261 h1.52
  text "BOTTOM" at 332.066,82.261 h1.52
  text "SILKSCREEN COLOR:" at 291.787,78.02 h1.52
  text "X" at 315.86,78.02 h1.52
  text "WHITE" at 319.086,78.02 h1.52
  text "OTHER" at 332.066,78.02 h1.52
  text "SOLDER RESIST COLOR:" at 291.787,73.702 h1.52
  text "X" at 306.208,69.658 h1.52
  text "GREEN" at 309.434,69.658 h1.52
  text "BLUE" at 324.446,69.658 h1.52
  text "OTHER" at 338.111,69.658 h1.52
  text "IMMERSION GOLD (ENIG)" at 314.794,64.87 h1.52
  text "ENEPIG" at 348.767,64.786 h1.52
  text "SURFACE FINISH:" at 287.844,64.761 h1.52
  text "X" at 310.045,64.761 h1.52
  text "IMM. TIN/SILVER OR EQUIV" at 296.215,60.773 h1.52
  text "OTHER" at 332.574,60.773 h1.52
  text "ARRAY/PANEL:" at 287.844,56.226 h1.52
  text "CUT AND TRIM PER MECH LAYER 1" at 314.794,56.118 h1.52
  text "N.C. ROUTE" at 314.794,52.264 h1.52
  text "X" at 332.04,52.264 h1.52
  text "V. SCORE" at 336.79,52.264 h1.52
  text "CERTIFICATION:" at 287.844,48.784 h1.52
  text "MATERIALS AND WORKMANSHIP FOR ALL PCBS" at 306.259,48.784 h1.52
  text "TO MEET OR EXCEED THE REQUIREMENTS OF:" at 306.259,46.295 h1.52
  text "X" at 296.773,42.828 h1.52
  text "ANSI IPC-A-600F CLASS ->" at 300.303,42.828 h1.52
  text "X" at 341.935,42.828 h1.52
  text "2" at 344.956,42.828 h1.52
  text "1" at 336.955,42.79 h1.52
  text "3" at 353.948,42.79 h1.52
  text "X" at 296.825,38.777 h1.52
  text "UL 94V-0" at 300.303,38.777 h1.52
  text "X" at 317.45,38.777 h1.52
  text "RoHS" at 320.928,38.777 h1.52
  text "OTHER" at 337.296,38.777 h1.52
  text "PER ORDER" at 347.381,38.777 h1.52
  text "ADDITIONAL REQUIREMENTS:" at 287.844,35.195 h1.52
  text "MICROSECTION:" at 289.744,32.274 h1.52
  text "YES" at 312.749,32.274 h1.52
  text "REQUIRED" at 334.631,28.308 h1.52
  text "BARE BOARD ELEC. TEST:" at 289.744,28.236 h1.52
  text "NONE" at 322.909,28.236 h1.52
  text "X" at 331.405,28.236 h1.52
  text "PER ORDER" at 349.668,28.236 h1.52
  text "MANUFACTURER'S UL:" at 289.744,24.248 h1.52
  text "RAIL" at 319.353,24.139 h1.52
  text "METAL" at 331.845,24.139 h1.52
  text "X" at 341.376,24.13 h1.52
  text "SILK" at 344.842,24.139 h1.52
  text ".Layer_Name" at 14.656,-21.806 h1.52
M11 Gerber Information:
  lines w0.254: -7.417,-23.626 160.223,-23.626 ; -7.417,-18.462 160.274,-18.462 ; -7.417,-13.297 -7.417,-28.791 94.31,-28.791 160.274,-28.791 160.274,-13.297 -7.404,-13.297 -7.404,-28.791 32.614,-28.791 ; 55.194,-28.791 55.194,-13.297 ; 87.376,-18.462 87.376,-13.297 ; 108.712,-18.462 108.712,-13.297 ; 124.511,-28.956 124.511,-23.804
  text "ALL ARTWORK VIEWED FROM TOP SIDE" at -5.804,-16.654 h1.52
  text "BOARD #:" at 57.099,-16.654 h1.52
  text ".PRJ_Number" at 70.955,-16.654 h1.52
  text "REV:" at 92.405,-16.654 h1.52
  text ".PCB_Rev" at 99.809,-16.654 h1.52
  text "SVN REV:" at 113.69,-16.654 h1.52
  text ".VersionControl_RevNumber" at 126.543,-16.654 h1.52
  text "LAYER NAME =" at -5.804,-21.806 h1.52
  text "TID #:" at 57.099,-21.819 h1.52
  text ".TID" at 70.955,-21.819 h1.52
  text "PLOT NAME =" at -5.804,-27.034 h1.52
  text ".plot_File_Name" at 14.656,-27.034 h1.52
  text "GENERATED    :" at 57.15,-27.034 h1.52
  text ".Print_Date" at 79.235,-27.034 h1.52
  text ".Print_Time" at 97.752,-27.034 h1.52
  text "TEXAS INSTRUMENTS" at 129.87,-27.034 h1.52
M12 Stackup:
  drawing of 191 lines, arcs and shapes, not listed
  text "Layer" at 248.681,198.882 h1.52
  text "Name" at 259.092,198.882 h1.52
  text "Material" at 282.708,198.882 h1.52
  text "Thickness" at 304.546,198.882 h1.52
  text "Constant" at 321.052,198.882 h1.52
  text "Board Layer Stack" at 335.526,198.882 h1.52
  text "1" at 248.681,195.834 h1.52
  text "Top Overlay" at 259.092,195.834 h1.52
  text "2" at 248.681,192.786 h1.52
  text "Top Solder" at 259.092,192.786 h1.52
  text "Solder Resist" at 282.708,192.786 h1.52
  text "0.40mil" at 304.546,192.786 h1.52
  text "3.5" at 321.052,192.786 h1.52
  text "3" at 248.681,189.738 h1.52
  text "Top Layer" at 259.092,189.738 h1.52
  text "Copper" at 282.708,189.738 h1.52
  text "1.40mil" at 304.546,189.738 h1.52
  text "4" at 248.681,186.69 h1.52
  text "Dielectric1" at 259.092,186.69 h1.52
  text "FR-4" at 282.708,186.69 h1.52
  text "59.20mil" at 304.546,186.69 h1.52
  text "4.8" at 321.052,186.69 h1.52
  text "5" at 248.681,183.642 h1.52
  text "Bottom Layer" at 259.092,183.642 h1.52
  text "Copper" at 282.708,183.642 h1.52
  text "1.40mil" at 304.546,183.642 h1.52
  text "6" at 248.681,180.594 h1.52
  text "Bottom Solder" at 259.092,180.594 h1.52
  text "Solder Resist" at 282.708,180.594 h1.52
  text "0.40mil" at 304.546,180.594 h1.52
  text "3.5" at 321.052,180.594 h1.52
  text "7" at 248.681,177.546 h1.52
  text "Bottom Overlay" at 259.092,177.546 h1.52
  text ".Layer_Name" at 14.656,-21.806 h1.52
M13 Component Bodies Top:
  text ".Layer_Name" at 14.656,-21.806 h1.52
M14 Component Bodies Bottom:
  text ".Layer_Name" at 14.656,-21.806 h1.52
M15 Courtyards Top:
  text ".Layer_Name" at 14.656,-21.806 h1.52
M16 Courtyards Bottom:
  text ".Layer_Name" at 14.656,-21.806 h1.52
Drill Drawing:
  circle w0.025: c141.549,51.439 r0.633
  circle w0.025: c141.549,51.439 r0.38
  circle w0.025: c141.549,81.809 r0.633
  lines w0.025: 140.916,39.734 141.233,40.05 140.916,40.367 141.233,40.367 141.549,40.683 141.865,40.367 142.182,40.367 141.865,40.05 142.182,39.734 141.865,39.734 141.549,39.418 141.233,39.734 140.916,39.734 ; 140.916,43.214 140.916,44.479 142.182,44.479 142.182,43.214 140.916,43.214 ; 140.916,48.276 141.549,47.01 142.182,48.276 140.916,48.276 ; 140.916,54.603 140.916,55.868 142.182,55.868 142.182,54.603 140.916,54.603 ; 140.916,59.032 141.549,59.664 142.182,59.032 141.549,58.399 140.916,59.032 ; 140.916,62.195 141.233,62.195 141.549,62.511 141.865,62.195 142.182,62.195 142.182,62.511 141.865,62.828 142.182,63.144 142.182,63.461 141.865,63.461 141.549,63.144 141.233,63.461 140.916,63.461 140.916,63.144 141.233,62.828 140.916,62.511 140.916,62.195 ; 140.916,66.308 140.916,66.94 141.233,66.94 141.233,67.257 141.865,67.257 141.865,66.94 142.182,66.94 142.182,66.308 141.865,66.308 141.865,65.991 141.233,65.991 141.233,66.308 140.916,66.308 ; 140.916,69.788 141.233,70.42 140.916,71.053 141.549,70.737 142.182,71.053 141.865,70.42 142.182,69.788 141.549,70.104 140.916,69.788 ; 140.916,73.9 141.233,74.217 140.916,74.533 141.233,74.533 141.549,74.849 141.865,74.533 142.182,74.533 141.865,74.217 142.182,73.9 141.865,73.9 141.549,73.584 141.233,73.9 140.916,73.9 ; 140.916,78.646 141.549,77.38 142.182,78.646 140.916,78.646 ; 141.169,39.861 141.359,40.05 141.169,40.24 141.359,40.24 141.549,40.43 141.739,40.24 141.929,40.24 141.739,40.05 141.929,39.861 141.739,39.861 141.549,39.671 141.359,39.861 141.169,39.861 ; 141.169,48.022 141.549,47.263 141.929,48.022 141.169,48.022 ; 141.169,54.856 141.169,55.615 141.929,55.615 141.929,54.856 141.169,54.856
  lines w0.305: 139.192,38.279 193.025,38.279 ; 139.192,83.834 193.025,83.834 ; 148.607,34.482 148.607,87.63 ; 157.678,34.482 157.678,87.63 ; 174.493,34.482 174.493,87.63 ; 181.715,34.482 181.715,87.63 ; 139.192,34.482 139.192,87.63 193.025,87.63 193.025,34.482 139.192,34.482
  text "Symbol" at 141.47,84.973 h1.83
  text "Quantity" at 149.746,84.973 h1.83
  text "Finished Hole Size" at 158.817,84.973 h1.83
  text "Plated" at 175.631,84.973 h1.83
  text "Hole Type" at 182.854,84.973 h1.83
  text "2" at 149.746,81.176 h1.52
  text "28.00mil (0.711mm)" at 158.817,81.176 h1.52
  text "PTH" at 175.631,81.176 h1.52
  text "Round" at 182.854,81.176 h1.52
  text "26" at 149.746,77.38 h1.52
  text "39.37mil (1.000mm)" at 158.817,77.38 h1.52
  text "PTH" at 175.631,77.38 h1.52
  text "Round" at 182.854,77.38 h1.52
  text "10" at 149.746,73.584 h1.52
  text "40.00mil (1.016mm)" at 158.817,73.584 h1.52
  text "PTH" at 175.631,73.584 h1.52
  text "Round" at 182.854,73.584 h1.52
  text "2" at 149.746,69.788 h1.52
  text "43.31mil (1.100mm)" at 158.817,69.788 h1.52
  text "PTH" at 175.631,69.788 h1.52
  text "Round" at 182.854,69.788 h1.52
  text "2" at 149.746,65.991 h1.52
  text "47.24mil (1.200mm)" at 158.817,65.991 h1.52
  text "PTH" at 175.631,65.991 h1.52
  text "Round" at 182.854,65.991 h1.52
  text "8" at 149.746,62.195 h1.52
  text "51.18mil (1.300mm)" at 158.817,62.195 h1.52
  text "PTH" at 175.631,62.195 h1.52
  text "Round" at 182.854,62.195 h1.52
  text "6" at 149.746,58.399 h1.52
  text "59.06mil (1.500mm)" at 158.817,58.399 h1.52
  text "PTH" at 175.631,58.399 h1.52
  text "Round" at 182.854,58.399 h1.52
  text "2" at 149.746,54.603 h1.52
  text "62.99mil (1.600mm)" at 158.817,54.603 h1.52
  text "PTH" at 175.631,54.603 h1.52
  text "Round" at 182.854,54.603 h1.52
  text "10" at 149.746,50.806 h1.52
  text "74.80mil (1.900mm)" at 158.817,50.806 h1.52
  text "PTH" at 175.631,50.806 h1.52
  text "Round" at 182.854,50.806 h1.52
  text "3" at 149.746,47.01 h1.52
  text "106.30mil (2.700mm)" at 158.817,47.01 h1.52
  text "PTH" at 175.631,47.01 h1.52
  text "Round" at 182.854,47.01 h1.52
  text "4" at 149.746,43.214 h1.52
  text "125.98mil (3.200mm)" at 158.817,43.214 h1.52
  text "PTH" at 175.631,43.214 h1.52
  text "Round" at 182.854,43.214 h1.52
  text "6" at 149.746,39.418 h1.52
  text "78.74mil (2.000mm)" at 158.817,39.418 h1.52
  text "PTH" at 175.631,39.418 h1.52
  text "Slot" at 182.854,39.418 h1.52
  text "81 Total" at 149.746,35.621 h1.52
  text ".Layer_Name" at 14.656,-21.806 h1.52

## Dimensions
0,0 to 215,0 on M2 Board Dimensions
0,0 to 0,145 on M2 Board Dimensions
0,-10.16 to 25.4,-10.16 on M2 Board Dimensions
